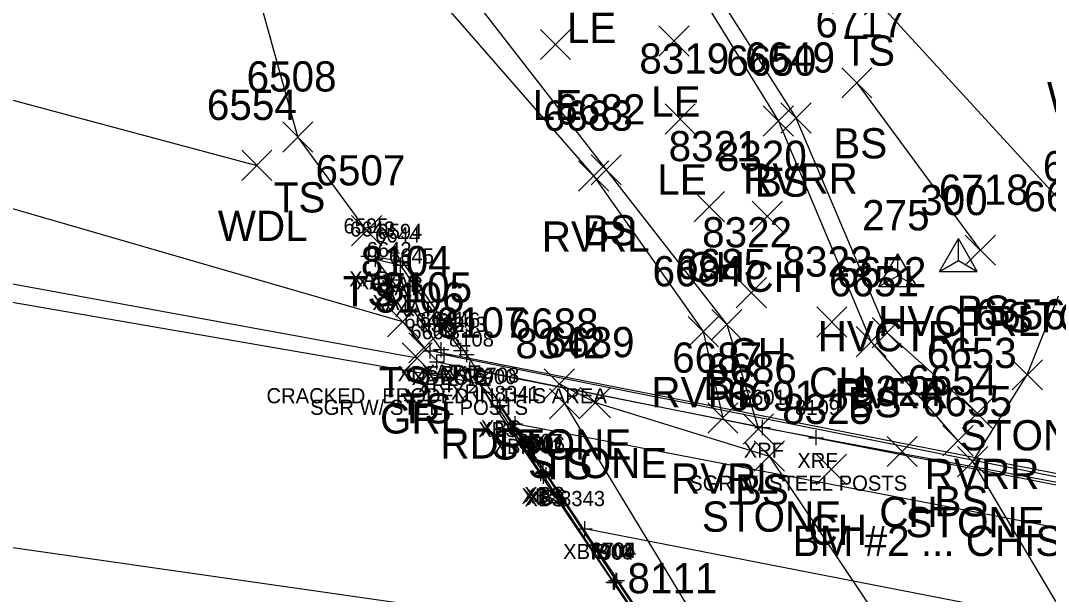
# Model space of a CAD drawing. Extents: x 1588028 to 1589597, y 137576 to 138176.
# Drawn here: x 1588875.5 to 1588943.5, y 137866.8 to 137904.7 of the extents above; entities that cross this region are included whole.
import ezdxf

# ---------------------------------------------------------------- set-up
doc = ezdxf.new("R2010")
doc.units = 0
for name, color, linetype in [('B_A', 7, 'Continuous'), ('B_C', 7, 'Continuous'), ('B_I', 7, 'Continuous'), ('B_TIC', 7, 'Continuous'), ('BB', 7, 'Continuous'), ('BELB', 7, 'Continuous'), ('BR', 7, 'Continuous'), ('BSE', 7, 'Continuous'), ('BSUBM', 7, 'Continuous'), ('C_A', 7, 'Continuous'), ('C_C', 7, 'Continuous'), ('C_I', 7, 'Continuous'), ('CPSM', 7, 'Continuous'), ('L_A', 7, 'Continuous'), ('L_I', 7, 'Continuous'), ('L_TIC', 7, 'Continuous'), ('LASF', 7, 'Continuous'), ('LAWA', 7, 'Continuous'), ('LAWE', 7, 'Continuous'), ('LELB', 7, 'Continuous'), ('P_A', 7, 'Continuous'), ('P_I', 7, 'Continuous'), ('P_TIC', 7, 'Continuous'), ('PET', 7, 'Continuous'), ('PRC', 7, 'Continuous'), ('R_A', 7, 'Continuous'), ('R_I', 7, 'Continuous'), ('R_TIC', 7, 'Continuous'), ('RGR', 7, 'Continuous')]:
    doc.layers.add(name, color=color, linetype=linetype)

msp = doc.modelspace()

# ---------------------------------------------------------------- linework, layer by layer
at = {"layer": 'B_TIC'}
for p, q in [((1588898.553, 137889.157), (1588898.629, 137889.157)), ((1588899.012, 137888.952), (1588899.088, 137888.952)), ((1588900.667, 137888.558), (1588900.743, 137888.558)), ((1588900.794, 137888.794), (1588900.87, 137888.794)), ((1588900.102, 137887.591), (1588900.178, 137887.591)), ((1588901.588, 137887.163), (1588901.664, 137887.163)), ((1588903.36, 137882.975), (1588903.436, 137882.975)), ((1588904.668, 137882.924), (1588904.743, 137882.924)), ((1588902.637, 137882.887), (1588902.713, 137882.887)), ((1588903.562, 137882.636), (1588903.638, 137882.636)), ((1588905.052, 137882.647), (1588905.128, 137882.647)), ((1588903.081, 137882.159), (1588903.157, 137882.159)), ((1588905.259, 137881.675), (1588905.334, 137881.675)), ((1588907.076, 137879.191), (1588907.151, 137879.191)), ((1588907.241, 137879.288), (1588907.317, 137879.288)), ((1588908.245, 137878.076), (1588908.32, 137878.076)), ((1588924.612, 137877.821), (1588924.688, 137877.821)), ((1588928.154, 137877.145), (1588928.23, 137877.145)), ((1588909.945, 137874.794), (1588910.021, 137874.794)), ((1588910.115, 137874.897), (1588910.19, 137874.897)), ((1588910.131, 137874.607), (1588910.206, 137874.607)), ((1588910.299, 137874.708), (1588910.374, 137874.708)), ((1588912.854, 137871.124), (1588912.929, 137871.124)), ((1588914.757, 137867.602), (1588914.833, 137867.602)), ((1588914.826, 137867.578), (1588914.902, 137867.578)), ((1588914.925, 137867.712), (1588915, 137867.712)), ((1588914.988, 137867.694), (1588915.063, 137867.694))]:
    msp.add_line(p, q, dxfattribs=at)
for points in [[(1588898.05, 137889.157), (1588899.05, 137889.157)], [(1588898.55, 137888.657), (1588898.55, 137889.657)], [(1588899.009, 137888.452), (1588899.009, 137889.452)], [(1588900.664, 137888.058), (1588900.664, 137889.058)], [(1588900.791, 137888.294), (1588900.791, 137889.294)], [(1588898.509, 137888.952), (1588899.509, 137888.952)], [(1588900.164, 137888.558), (1588901.164, 137888.558)], [(1588900.291, 137888.794), (1588901.291, 137888.794)], [(1588900.099, 137887.091), (1588900.099, 137888.091)], [(1588899.599, 137887.591), (1588900.599, 137887.591)], [(1588901.085, 137887.163), (1588902.085, 137887.163)], [(1588901.585, 137886.663), (1588901.585, 137887.663)], [(1588902.634, 137882.387), (1588902.634, 137883.387)], [(1588902.857, 137882.975), (1588903.857, 137882.975)], [(1588903.357, 137882.475), (1588903.357, 137883.475)], [(1588903.559, 137882.136), (1588903.559, 137883.136)], [(1588904.164, 137882.924), (1588905.164, 137882.924)], [(1588904.664, 137882.424), (1588904.664, 137883.424)], [(1588905.049, 137882.147), (1588905.049, 137883.147)], [(1588902.134, 137882.887), (1588903.134, 137882.887)], [(1588903.059, 137882.636), (1588904.059, 137882.636)], [(1588903.078, 137881.659), (1588903.078, 137882.659)], [(1588904.549, 137882.647), (1588905.549, 137882.647)], [(1588902.578, 137882.159), (1588903.578, 137882.159)], [(1588904.755, 137881.675), (1588905.755, 137881.675)], [(1588905.255, 137881.175), (1588905.255, 137882.175)], [(1588907.072, 137878.691), (1588907.072, 137879.691)], [(1588907.238, 137878.788), (1588907.238, 137879.788)], [(1588906.572, 137879.191), (1588907.572, 137879.191)], [(1588906.738, 137879.288), (1588907.738, 137879.288)], [(1588908.241, 137877.576), (1588908.241, 137878.576)], [(1588924.609, 137877.321), (1588924.609, 137878.321)], [(1588907.741, 137878.076), (1588908.741, 137878.076)], [(1588924.109, 137877.821), (1588925.109, 137877.821)], [(1588928.151, 137876.645), (1588928.151, 137877.645)], [(1588927.651, 137877.145), (1588928.651, 137877.145)], [(1588909.442, 137874.794), (1588910.442, 137874.794)], [(1588909.612, 137874.897), (1588910.612, 137874.897)], [(1588909.942, 137874.294), (1588909.942, 137875.294)], [(1588910.112, 137874.397), (1588910.112, 137875.397)], [(1588910.127, 137874.107), (1588910.127, 137875.107)], [(1588910.295, 137874.208), (1588910.295, 137875.208)], [(1588909.627, 137874.607), (1588910.627, 137874.607)], [(1588909.795, 137874.708), (1588910.795, 137874.708)], [(1588912.85, 137870.624), (1588912.85, 137871.624)], [(1588912.35, 137871.124), (1588913.35, 137871.124)], [(1588914.754, 137867.102), (1588914.754, 137868.102)], [(1588914.823, 137867.078), (1588914.823, 137868.078)], [(1588914.921, 137867.212), (1588914.921, 137868.212)], [(1588914.984, 137867.194), (1588914.984, 137868.194)], [(1588914.254, 137867.602), (1588915.254, 137867.602)], [(1588914.323, 137867.578), (1588915.323, 137867.578)], [(1588914.421, 137867.712), (1588915.421, 137867.712)], [(1588914.484, 137867.694), (1588915.484, 137867.694)]]:
    msp.add_lwpolyline(points, dxfattribs=at)
at = {"layer": 'BB'}
for points in [[(1588954.992, 137869.089), (1588908.241, 137878.076)], [(1588959.799, 137861.973), (1588912.85, 137871.124)]]:
    msp.add_lwpolyline(points, dxfattribs=at)
at = {"layer": 'BELB'}
for points in [[(1588955.231, 137872.573), (1588902.634, 137882.887)], [(1588952.511, 137872.865), (1588903.559, 137882.636)]]:
    msp.add_lwpolyline(points, dxfattribs=at)
at = {"layer": 'BR'}
for points in [[(1588903.078, 137882.159), (1588924.609, 137877.821), (1588952.299, 137872.682)], [(1588905.255, 137881.675), (1588928.151, 137877.145), (1588951.93, 137872.493)]]:
    msp.add_lwpolyline(points, dxfattribs=at)
at = {"layer": 'BSE'}
msp.add_lwpolyline([(1588927.826, 137848.377), (1588924.416, 137853.54), (1588924.263, 137853.707), (1588919.622, 137860.635), (1588919.663, 137860.644), (1588914.984, 137867.694), (1588914.921, 137867.712), (1588910.295, 137874.708), (1588910.112, 137874.897), (1588907.238, 137879.288), (1588907.072, 137879.191), (1588909.942, 137874.794), (1588910.127, 137874.607), (1588914.754, 137867.602), (1588914.823, 137867.578), (1588919.488, 137860.544), (1588919.471, 137860.508), (1588924.091, 137853.616), (1588924.24, 137853.45), (1588927.661, 137848.28)], dxfattribs=at)
at = {"layer": 'BSUBM'}
for points in [[(1588931.875, 137839.494), (1588933.423, 137839.638), (1588929.998, 137845.393), (1588905.049, 137882.647), (1588900.791, 137888.794), (1588898.55, 137889.157)], [(1588903.357, 137882.975), (1588900.099, 137887.591), (1588899.009, 137888.952), (1588900.664, 137888.558), (1588901.585, 137887.163), (1588904.664, 137882.924)]]:
    msp.add_lwpolyline(points, dxfattribs=at)
at = {"layer": 'CPSM'}
for p, q in [((1588936.315, 137888.149), (1588937.565, 137890.314)), ((1588938.815, 137888.149), (1588937.565, 137890.314)), ((1588937.565, 137888.87), (1588937.565, 137890.314)), ((1588932.312, 137887.141), (1588933.562, 137889.306)), ((1588934.812, 137887.141), (1588933.562, 137889.306)), ((1588933.562, 137887.862), (1588933.562, 137889.306)), ((1588936.315, 137888.149), (1588937.565, 137888.87)), ((1588937.565, 137888.87), (1588937.565, 137888.87)), ((1588937.565, 137888.87), (1588938.815, 137888.149)), ((1588932.312, 137887.141), (1588933.562, 137887.862)), ((1588933.562, 137887.862), (1588933.562, 137887.862)), ((1588933.562, 137887.862), (1588934.812, 137887.141)), ((1588936.315, 137888.149), (1588938.815, 137888.149)), ((1588932.312, 137887.141), (1588934.812, 137887.141))]:
    msp.add_line(p, q, dxfattribs=at)
at = {"layer": 'L_TIC'}
for points in [[(1588909.922, 137902.154), (1588911.922, 137904.154)], [(1588911.922, 137902.154), (1588909.922, 137904.154)], [(1588917.755, 137902.379), (1588919.755, 137904.379)], [(1588919.755, 137902.379), (1588917.755, 137904.379)], [(1588929.852, 137899.621), (1588931.852, 137901.621)], [(1588931.852, 137899.621), (1588929.852, 137901.621)], [(1588925.819, 137897.295), (1588927.819, 137899.295)], [(1588927.819, 137897.295), (1588925.819, 137899.295)], [(1588918.165, 137897.227), (1588920.165, 137899.227)], [(1588920.165, 137897.227), (1588918.165, 137899.227)], [(1588924.659, 137897.089), (1588926.659, 137899.089)], [(1588926.659, 137897.089), (1588924.659, 137899.089)], [(1588892.874, 137896.045), (1588894.874, 137898.045)], [(1588894.874, 137896.045), (1588892.874, 137898.045)], [(1588890.167, 137894.163), (1588892.167, 137896.163)], [(1588892.167, 137894.163), (1588890.167, 137896.163)], [(1588913.271, 137893.866), (1588915.271, 137895.866)], [(1588915.271, 137893.866), (1588913.271, 137895.866)], [(1588912.444, 137893.451), (1588914.444, 137895.451)], [(1588914.444, 137893.451), (1588912.444, 137895.451)], [(1588920.095, 137891.437), (1588922.095, 137893.437)], [(1588922.095, 137891.437), (1588920.095, 137893.437)], [(1588923.937, 137890.795), (1588925.937, 137892.795)], [(1588925.937, 137890.795), (1588923.937, 137892.795)], [(1588897.429, 137889.835), (1588899.429, 137891.835)], [(1588899.429, 137889.835), (1588897.429, 137891.835)], [(1588938.012, 137888.552), (1588940.012, 137890.552)], [(1588940.012, 137888.552), (1588938.012, 137890.552)], [(1588922.875, 137885.734), (1588924.875, 137887.734)], [(1588924.875, 137885.734), (1588922.875, 137887.734)], [(1588899.808, 137883.827), (1588901.808, 137885.827)], [(1588901.808, 137883.827), (1588899.808, 137885.827)], [(1588928.198, 137883.798), (1588930.198, 137885.798)], [(1588930.198, 137883.798), (1588928.198, 137885.798)], [(1588919.693, 137883.162), (1588921.693, 137885.162)], [(1588921.693, 137883.162), (1588919.693, 137885.162)], [(1588921.254, 137883.638), (1588923.254, 137885.638)], [(1588923.254, 137883.638), (1588921.254, 137885.638)], [(1588931.856, 137883.092), (1588933.856, 137885.092)], [(1588933.856, 137883.092), (1588931.856, 137885.092)], [(1588930.797, 137882.497), (1588932.797, 137884.497)], [(1588932.797, 137882.497), (1588930.797, 137884.497)], [(1588901.224, 137882.092), (1588903.224, 137884.092)], [(1588903.224, 137882.092), (1588901.224, 137884.092)], [(1588941.12, 137880.309), (1588943.12, 137882.309)], [(1588943.12, 137880.309), (1588941.12, 137882.309)], [(1588910.174, 137879.705), (1588912.174, 137881.705)], [(1588912.174, 137879.705), (1588910.174, 137881.705)], [(1588910.531, 137878.394), (1588912.531, 137880.394)], [(1588912.531, 137878.394), (1588910.531, 137880.394)], [(1588912.559, 137878.473), (1588914.559, 137880.473)], [(1588914.559, 137878.473), (1588912.559, 137880.473)], [(1588937.828, 137877.755), (1588939.828, 137879.755)], [(1588939.828, 137877.755), (1588937.828, 137879.755)], [(1588920.989, 137877.448), (1588922.989, 137879.448)], [(1588922.989, 137877.448), (1588920.989, 137879.448)], [(1588923.341, 137876.721), (1588925.341, 137878.721)], [(1588925.341, 137876.721), (1588923.341, 137878.721)], [(1588936.541, 137875.947), (1588938.541, 137877.947)], [(1588938.541, 137875.947), (1588936.541, 137877.947)], [(1588924.059, 137874.931), (1588926.059, 137876.931)], [(1588926.059, 137874.931), (1588924.059, 137876.931)], [(1588932.848, 137875.238), (1588934.848, 137877.238)], [(1588934.848, 137875.238), (1588932.848, 137877.238)], [(1588937.518, 137874.567), (1588939.518, 137876.567)], [(1588939.518, 137874.567), (1588937.518, 137876.567)], [(1588928.17, 137874.06), (1588930.17, 137876.06)], [(1588930.17, 137874.06), (1588928.17, 137876.06)]]:
    msp.add_lwpolyline(points, dxfattribs=at)
at = {"layer": 'LASF'}
for points in [[(1588938.518, 137875.567), (1588942.12, 137881.309), (1588945.219, 137889.116), (1588947.914, 137881.079)], [(1588911.174, 137880.705), (1588913.559, 137879.473), (1588925.059, 137875.931), (1588937.221, 137857.788), (1588942.468, 137844.578), (1588934.714, 137844.887), (1588931.403, 137844.992)], [(1588956.515, 137845.255), (1588938.518, 137875.567)]]:
    msp.add_lwpolyline(points, dxfattribs=at)
at = {"layer": 'LAWA'}
msp.add_lwpolyline([(1588745.303, 137917.8), (1588775.383, 137912.97), (1588792.871, 137912.545), (1588815.254, 137908.882), (1588848.166, 137904.535), (1588870.635, 137900.637), (1588891.167, 137895.163)], dxfattribs=at)
at = {"layer": 'LAWE'}
for points in [[(1588434.557, 138062.893), (1588458.468, 138076.788), (1588495.544, 138110.891), (1588517.719, 138151.172), (1588540.379, 138168.377), (1588562.318, 138170.598), (1588586.159, 138148.713), (1588635.488, 138130.012), (1588676.052, 138127.985), (1588706.089, 138118.665), (1588727.823, 138096.854), (1588770.393, 138065.1), (1588798.796, 138043.179), (1588827.558, 138018.038), (1588869.93, 137975.121), (1588899.989, 137936.939), (1588912.075, 137921.496), (1588926.819, 137898.295), (1588932.856, 137884.092), (1588938.828, 137878.755)], [(1588441.022, 138044.541), (1588465.046, 138060.114), (1588492.426, 138083.391), (1588521.861, 138113.876), (1588530.723, 138143.537), (1588545.568, 138151.233), (1588554.849, 138142.988), (1588577.097, 138115.955), (1588614.25, 138110.978), (1588643.876, 138111.052), (1588664.407, 138106.886), (1588688.529, 138102.18), (1588718.752, 138082.483), (1588743.283, 138056.228), (1588764.526, 138038.439), (1588797.037, 138013.977), (1588814.468, 138001.044), (1588852.472, 137959.373), (1588883.947, 137928.089), (1588897.47, 137912.785), (1588913.444, 137894.451), (1588920.693, 137884.162), (1588921.989, 137878.448)]]:
    msp.add_lwpolyline(points, dxfattribs=at)
at = {"layer": 'LELB'}
for points in [[(1588682.047, 138125.085), (1588705.482, 138117.825), (1588727.758, 138095.081), (1588769.427, 138063.362), (1588798.462, 138041.61), (1588826.194, 138016.504), (1588867.283, 137972.838), (1588898.61, 137935.759), (1588911.419, 137921.164), (1588925.659, 137898.089), (1588931.797, 137883.497), (1588937.541, 137876.947)], [(1588898.429, 137890.835), (1588893.874, 137897.045), (1588887.933, 137918.514), (1588870.826, 137925.887), (1588860.156, 137926.877)], [(1588901.369, 137911.494), (1588914.271, 137894.866), (1588922.254, 137884.638), (1588924.341, 137877.721)], [(1588781.082, 137906.511), (1588804.646, 137907.229), (1588827.148, 137901.794), (1588865.923, 137894.936), (1588900.808, 137884.827), (1588902.224, 137883.092)], [(1588945.892, 137891.105), (1588931.552, 137906.749)], [(1588930.852, 137900.621), (1588939.012, 137889.552)], [(1588911.531, 137879.394), (1588931.773, 137845.978)]]:
    msp.add_lwpolyline(points, dxfattribs=at)
at = {"layer": 'P_TIC'}
for points in [[(1588904.816, 137879.769), (1588906.816, 137881.769)], [(1588906.816, 137879.769), (1588904.816, 137881.769)]]:
    msp.add_lwpolyline(points, dxfattribs=at)
at = {"layer": 'PET'}
msp.add_lwpolyline([(1588422.162, 137923.17), (1588469.198, 137920.726), (1588503.282, 137919.24), (1588517.546, 137918.562), (1588549.936, 137917.247), (1588592.353, 137915.11), (1588643.263, 137911.753), (1588663.499, 137910.854), (1588704.319, 137908.351), (1588747.195, 137904.384), (1588787.693, 137899.079), (1588825.325, 137893.626), (1588865.15, 137887.82), (1588905.816, 137880.769), (1588917.24, 137863.853), (1588927.992, 137847.51)], dxfattribs=at)
at = {"layer": 'PRC'}
msp.add_lwpolyline([(1588420.991, 137907.197), (1588467.18, 137904.915), (1588507.288, 137903.206), (1588549.369, 137901.189), (1588590.546, 137899.296), (1588641.569, 137896.105), (1588661.527, 137894.877), (1588702.386, 137891.263), (1588744.444, 137887.15), (1588784.396, 137882.299), (1588823.706, 137877.304), (1588862.063, 137871.744), (1588917.24, 137863.853)], dxfattribs=at)
at = {"layer": 'R_TIC'}
for points in [[(1588900.772, 137881.426), (1588902.772, 137883.426)], [(1588902.772, 137881.426), (1588900.772, 137883.426)]]:
    msp.add_lwpolyline(points, dxfattribs=at)
at = {"layer": 'RGR'}
msp.add_lwpolyline([(1588803.426, 137901.36), (1588825.052, 137896.506), (1588842.533, 137892.864), (1588864.375, 137889.261), (1588901.772, 137882.426)], dxfattribs=at)

# ---------------------------------------------------------------- texts
at = {"layer": 'B_A'}
for s, p in [('XAB', (1588897.27, 137887.157)), ('XAT', (1588897.713, 137886.952)), ('XAB', (1588899.511, 137886.794)), ('XAT', (1588899.369, 137886.558)), ('XAT', (1588898.804, 137885.591)), ('XAT', (1588900.289, 137885.163)), ('XDECK', (1588900.476, 137880.887)), ('XDECK', (1588901.401, 137880.636)), ('XAT', (1588902.062, 137880.975)), ('XAT', (1588903.369, 137880.924)), ('XAB', (1588903.769, 137880.647)), ('XRF', (1588901.838, 137880.159)), ('XRF', (1588904.015, 137879.675)), ('XBS', (1588905.813, 137877.191)), ('XBS', (1588905.978, 137877.288)), ('XBIB', (1588906.812, 137876.076)), ('XRF', (1588923.369, 137875.821)), ('XRF', (1588926.911, 137875.145)), ('XBS', (1588908.682, 137872.794)), ('XBS', (1588908.852, 137872.897)), ('XBS', (1588908.867, 137872.607)), ('XBS', (1588909.035, 137872.708)), ('XBIB', (1588911.421, 137869.124))]:
    msp.add_text(s, height=1, dxfattribs=at).set_placement(p)
at = {"layer": 'B_C'}
for s, p in [('CRACKED   ERODED IN THIS AREA', (1588891.802, 137879.424)), ('SGR W/ STEEL POSTS', (1588894.692, 137878.659)), ('SGR W/ STEEL POSTS', (1588919.765, 137873.645))]:
    msp.add_text(s, height=1, dxfattribs=at).set_placement(p)
at = {"layer": 'B_I'}
for s, p in [('6595', (1588896.896, 137890.657)), ('6643', (1588897.332, 137890.452)), ('6594', (1588899.137, 137890.294)), ('6644', (1588898.987, 137890.058)), ('6642', (1588898.422, 137889.091)), ('6645', (1588899.907, 137888.663)), ('6640', (1588900.913, 137884.387)), ('8382', (1588901.929, 137884.136)), ('6641', (1588901.963, 137884.475)), ('6646', (1588902.96, 137884.424)), ('6593', (1588903.395, 137884.147)), ('6600', (1588901.318, 137883.659)), ('8108', (1588903.87, 137883.175)), ('7900', (1588905.36, 137880.691)), ('6708', (1588905.545, 137880.788)), ('8341', (1588906.895, 137879.576)), ('6601', (1588923.176, 137879.321)), ('8109', (1588926.761, 137878.645)), ('6707', (1588908.419, 137876.397)), ('7902', (1588908.458, 137876.107)), ('7901', (1588908.556, 137876.294)), ('6706', (1588908.575, 137876.208)), ('8343', (1588911.22, 137872.624)), ('7903', (1588913.085, 137869.102)), ('7904', (1588913.153, 137869.078)), ('6705', (1588913.228, 137869.212)), ('6704', (1588913.291, 137869.194))]:
    msp.add_text(s, height=1, dxfattribs=at).set_placement(p)
at = {"layer": 'C_A'}
for p in [(1588932.258, 137883.87), (1588928.255, 137882.862)]:
    msp.add_text('HVCTRL', height=2, dxfattribs=at).set_placement(p)
at = {"layer": 'C_C'}
msp.add_text('BM #2 ... CHISELED SQ IN CRN', height=2, dxfattribs=at).set_placement((1588926.611, 137869.322))
at = {"layer": 'C_I'}
for s, p in [('300', (1588935.038, 137891.87)), ('275', (1588931.2, 137890.862))]:
    msp.add_text(s, height=2, dxfattribs=at).set_placement(p)
at = {"layer": 'L_A'}
for s, p in [('LE', (1588911.674, 137903.262)), ('TS', (1588929.962, 137901.749)), ('WDR', (1588943.433, 137898.665)), ('LE', (1588909.41, 137898.154)), ('LE', (1588917.243, 137898.379)), ('BS', (1588929.293, 137895.621)), ('LE', (1588917.653, 137893.227)), ('RVRR', (1588923.331, 137893.295)), ('BS', (1588924.1, 137893.089)), ('TS', (1588892.283, 137892.045)), ('WDL', (1588888.584, 137890.163)), ('BS', (1588912.712, 137889.866)), ('RVRL', (1588910.011, 137889.451)), ('CH', (1588919.583, 137887.437)), ('CH', (1588923.425, 137886.795)), ('TS', (1588896.839, 137885.835)), ('BS', (1588937.453, 137884.552)), ('STONE', (1588940.763, 137884.116)), ('CH', (1588922.363, 137881.734)), ('TS', (1588899.218, 137879.827)), ('BS', (1588920.695, 137879.638)), ('CH', (1588927.686, 137879.798)), ('RVRL', (1588917.26, 137879.162)), ('RVRR', (1588929.367, 137879.092)), ('BS', (1588930.238, 137878.497)), ('TS', (1588900.633, 137878.092)), ('STONE', (1588937.664, 137876.309)), ('STONE', (1588906.718, 137875.705)), ('STONE', (1588909.103, 137874.473)), ('TS', (1588909.94, 137874.394)), ('RVRL', (1588918.556, 137873.448)), ('RVRR', (1588935.34, 137873.755)), ('BS', (1588922.782, 137872.721)), ('BS', (1588935.982, 137871.947)), ('STONE', (1588920.602, 137870.931)), ('CH', (1588932.336, 137871.238)), ('CH', (1588927.658, 137870.06)), ('STONE', (1588934.061, 137870.567))]:
    msp.add_text(s, height=2, dxfattribs=at).set_placement(p)
at = {"layer": 'L_I'}
for s, p in [('6717', (1588928.112, 137903.621)), ('6649', (1588923.457, 137901.295)), ('8319', (1588916.464, 137901.227)), ('6650', (1588922.218, 137901.089)), ('6508', (1588890.488, 137900.045)), ('6554', (1588887.86, 137898.163)), ('6683', (1588910.09, 137897.451)), ('6682', (1588910.917, 137897.866)), ('8321', (1588918.402, 137895.437)), ('8320', (1588921.591, 137894.795)), ('6507', (1588895.043, 137893.835)), ('6715', (1588943.152, 137894.105)), ('6718', (1588936.272, 137892.552)), ('6657', (1588941.865, 137892.116)), ('8322', (1588920.615, 137889.734)), ('8104', (1588898.037, 137887.827)), ('8323', (1588925.938, 137887.798)), ('6684', (1588917.338, 137887.162)), ('6685', (1588918.9, 137887.638)), ('6652', (1588929.501, 137887.092)), ('6651', (1588929.009, 137886.497)), ('8105', (1588899.452, 137886.092)), ('6656', (1588938.711, 137884.309)), ('6688', (1588907.82, 137883.705)), ('8342', (1588908.271, 137882.394)), ('6689', (1588910.197, 137882.473)), ('6653', (1588935.474, 137881.755)), ('6687', (1588918.635, 137881.448)), ('6686', (1588920.932, 137880.721)), ('6654', (1588934.186, 137879.947)), ('6691', (1588922.271, 137878.931)), ('8324', (1588930.588, 137879.238)), ('6655', (1588935.164, 137878.567)), ('8325', (1588925.91, 137878.06))]:
    msp.add_text(s, height=2, dxfattribs=at).set_placement(p)
at = {"layer": 'P_A'}
msp.add_text('RDP', height=2, dxfattribs=at).set_placement((1588903.304, 137875.769))
at = {"layer": 'P_I'}
for s, p in [('8107', (1588903.044, 137883.769)), ('8111', (1588915.681, 137866.853)), ('8111', (1588915.681, 137866.853))]:
    msp.add_text(s, height=2, dxfattribs=at).set_placement(p)
at = {"layer": 'R_A'}
msp.add_text('GRL', height=2, dxfattribs=at).set_placement((1588899.315, 137877.426))
at = {"layer": 'R_I'}
msp.add_text('8106', height=2, dxfattribs=at).set_placement((1588898.945, 137885.426))

doc.saveas('drawing.dxf')
